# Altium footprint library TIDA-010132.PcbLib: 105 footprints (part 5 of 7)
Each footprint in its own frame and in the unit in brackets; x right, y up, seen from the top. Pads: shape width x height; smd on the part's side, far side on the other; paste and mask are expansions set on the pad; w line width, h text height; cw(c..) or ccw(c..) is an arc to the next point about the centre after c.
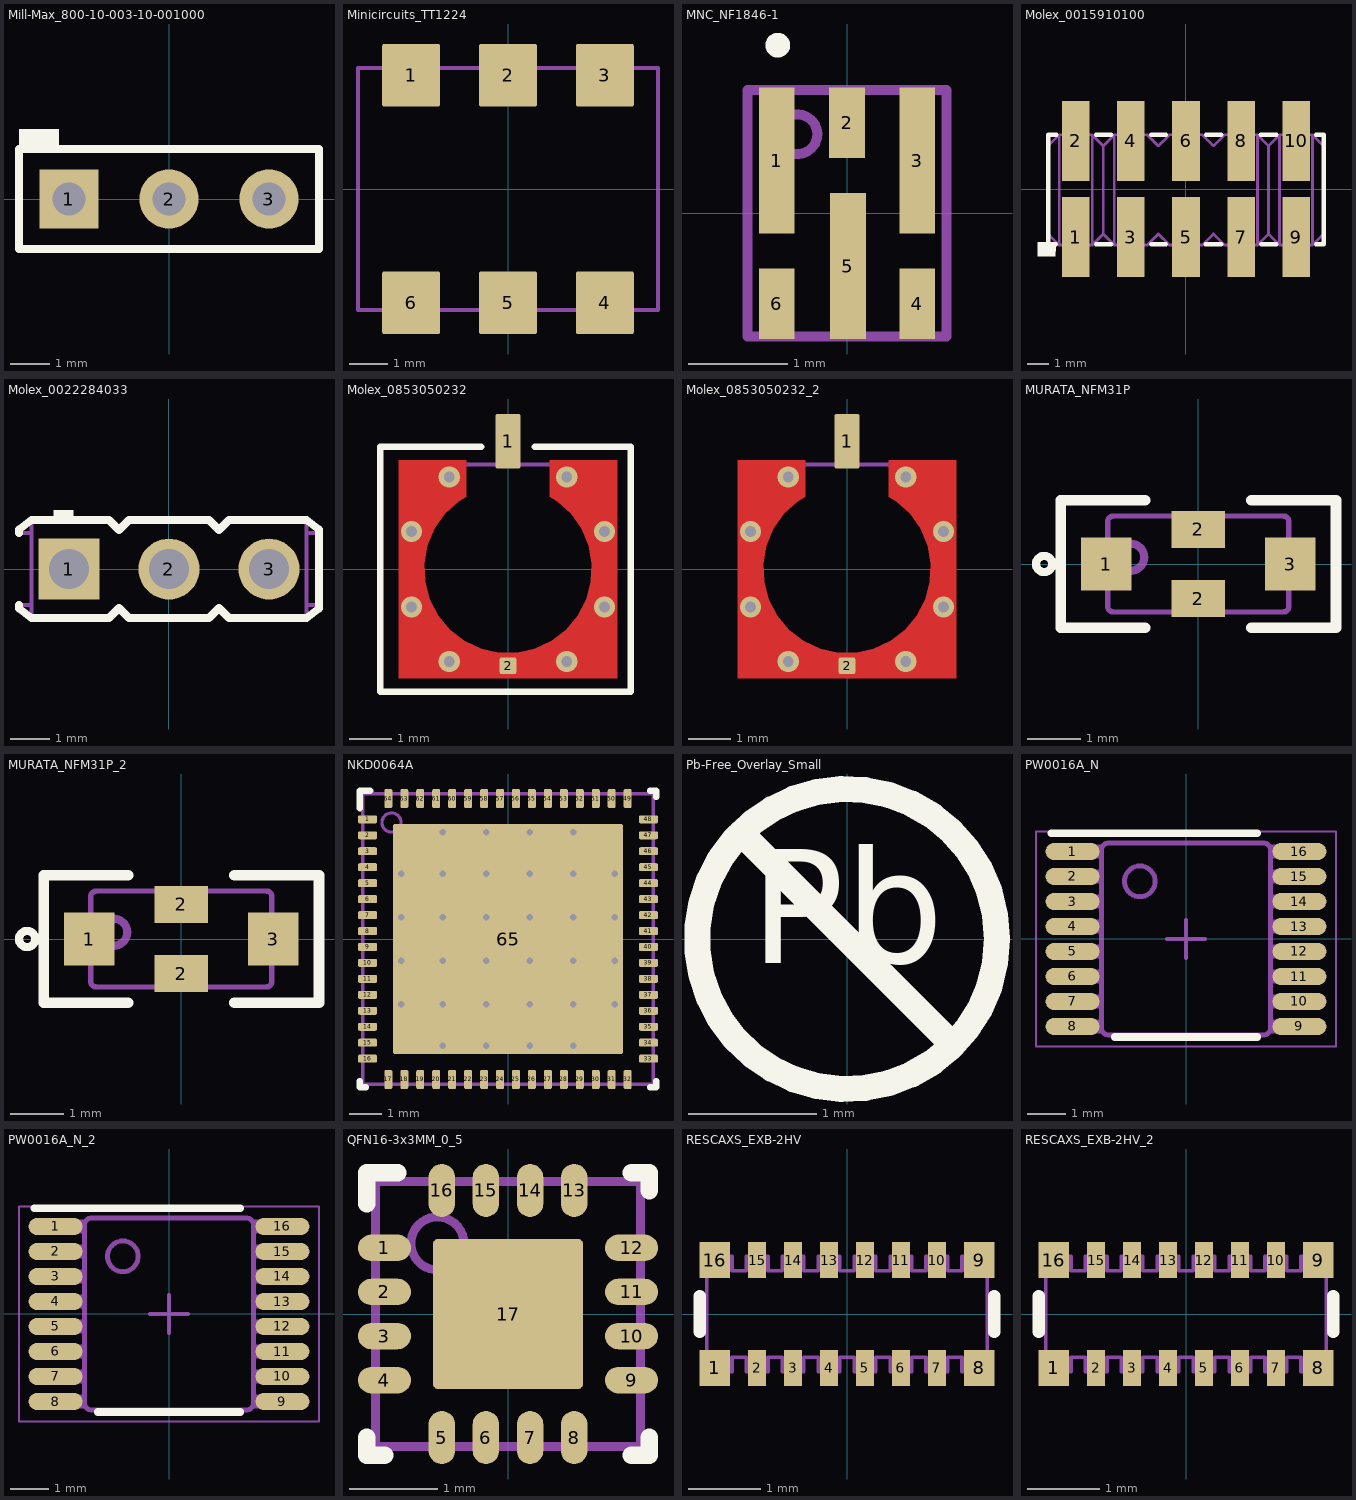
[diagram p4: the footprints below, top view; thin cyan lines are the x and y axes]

## Mill-Max_800-10-003-10-001000 [mm] "Mill-Max"
height 8.128
pads (3):
  rect 1.5x1.5 hole 0.85: 1(-2.54,0)
  round 1.5 hole 0.85: 2(0,0) 3(2.54,0)
Top Overlay:
  rectangle: -3.81,1.27 -2.794,1.778
  lines w0.203: -3.81,-1.27 3.81,-1.27 3.81,1.27 -3.81,1.27 -3.81,-1.27
Mechanical 5:
  lines w0.102: -3.81,-1.27 -3.81,1.27 3.81,1.27 3.81,-1.27 -3.81,-1.27
  text ".Designator" at -2.032,-0.508 h0.46
3D body: height 8.13, standoff 0, extent 2.162,-0.38 2.921,0.38
3D body: height 8.13, standoff 0, extent -0.378,-0.38 0.381,0.38
3D body: height 8.13, standoff 0, extent -2.918,-0.38 -2.159,0.38
3D body: height 0.81, standoff -3, extent 2.238,-0.304 2.845,0.304
3D body: height 0.81, standoff -3, extent -0.302,-0.304 0.305,0.304
3D body: height 0.81, standoff -3, extent -2.842,-0.304 -2.235,0.304
3D body: height 3.17, standoff 0, extent -3.809,-1.269 3.809,1.269

## Minicircuits_TT1224 [mm] "SMD, 6-Leads, Body 7.87x6.35mm"
height 4.06
pads (6):
  rrect7% 1.52x1.65 smd: 1(-2.54,2.985) 2(0,2.985) 3(2.54,2.985) 4(2.54,-2.985) 5(0,-2.985) 6(-2.54,-2.985)
Mechanical 5:
  lines w0.1: -3.935,-3.175 3.935,-3.175 3.935,3.175 -3.935,3.175 -3.935,-3.175
  text ".Designator" at -1.8,-0.514 h0.46
3D body: height 4.06, standoff 0, extent -3.935,-3.175 3.935,3.175

## MNC_NF1846-1 [mm] "SMD, 6-Leads, Body 2.01x2.49mm"
height 0.89
pads (6):
  rect 0.36x1.475 smd: 1(-0.71,0.533) 3(0.71,0.533) 5(0.01,-0.533)
  rect 0.36x0.71 smd: 2(0,0.915) 4(0.71,-0.915) 6(-0.71,-0.915)
Top Overlay:
  circle w0.125: c-0.7,1.7 r0.062
Mechanical 5:
  circle w0.1: c-0.5,0.8 r0.2
  lines w0.1: -1.005,-1.245 -1.005,1.245 1.005,1.245 1.005,-1.245 -1.005,-1.245
  text ".Designator" at -0.9,-0.2 h0.46
3D body: height 0.89, standoff 0, extent -1.005,-1.245 1.005,1.245
3D body: height 0.89, standoff 0.89, extent -0.699,0.601 -0.301,0.999

## Molex_0015910100 [mm] "MOLEX"
height 9.7
pads (10):
  rect 1.27x3.68 smd: 1(-5.08,-2.22) 2(-5.08,2.22) 3(-2.54,-2.22) 4(-2.54,2.22) 5(0,-2.22) 6(0,2.22) 7(2.54,-2.22) 8(2.54,2.22) 9(5.08,-2.22) 10(5.08,2.22)
Top Overlay:
  rectangle: -6.85,-3.125 -6.025,-2.45
  rectangle: -6.6,-2.875 -6,-2.45
  lines w0.2: -6,-2.55 -6.35,-2.55 -6.35,2.5 -5.975,2.5 ; -4.15,-2.55 -3.45,-2.55 ; -4.15,2.5 -3.45,2.5 ; -1.6,-2.55 -0.925,-2.55 ; -1.6,2.5 -0.925,2.5 ; 0.9,-2.55 1.625,-2.55 ; 0.925,2.5 1.625,2.5 ; 3.45,2.5 4.175,2.5 ; 3.475,-2.55 4.175,-2.55 ; 6,-2.55 6.35,-2.55 6.35,2.5 6,2.5
Mechanical 5:
  drawing of 220 lines, arcs and shapes, not listed
  text ".Designator" at -1.9,-0.525 h0.46
3D body "015910100.stp": height 9.64, standoff -0.01, extent -6.35,-3.492 6.35,3.493

## Molex_0022284033 [mm] "Header, 2.54mm, 3x1, TH"
height 8.88
pads (3):
  rect 1.55x1.55 hole 1.02: 1(-2.54,0)
  round 1.55 hole 1.02: 2(0,0) 3(2.54,0)
Top Overlay:
  rectangle: -2.93,1.245 -2.43,1.5
  lines w0.2: -3.81,-0.914 -3.81,-1.003 -3.493,-1.245 -1.524,-1.245 -1.27,-0.991 -1.016,-1.245 1.016,-1.245 1.27,-0.991 1.524,-1.245 3.493,-1.245 3.81,-1.003 3.81,-0.914 3.81,0.914 3.81,1.003 3.492,1.245 1.524,1.245 1.27,0.991 1.016,1.245 -1.016,1.245 -1.27,0.991 -1.524,1.245 -3.493,1.245 -3.81,1.003 -3.81,0.914
Mechanical 5:
  lines w0.1: -3.493,-1.168 -3.493,1.168 ; -3.492,-0.914 -3.81,-0.914 -3.81,-1.003 -3.493,-1.245 -1.524,-1.245 -1.27,-0.991 -1.016,-1.245 1.016,-1.245 1.27,-0.991 1.524,-1.245 3.493,-1.245 3.81,-1.003 3.81,-0.914 ; -3.492,0.914 -3.81,0.914 -3.81,1.003 -3.493,1.245 -1.524,1.245 -1.27,0.991 -1.016,1.245 1.016,1.245 1.27,0.991 1.524,1.245 3.492,1.245 3.81,1.003 3.81,0.914 ; 3.492,-1.168 3.492,1.168 ; 3.492,-0.914 3.81,-0.914 ; 3.492,0.914 3.81,0.914 ; 3.81,-0.914 3.81,0.914
  text ".Designator" at -2,-0.7 h0.46
3D body "022284033.stp": height 8.4, standoff -3.16, extent -3.81,-1.244 3.81,1.245

## Molex_0853050232 [mm] "Plug, 50 Ohm, Straight, SMT"
height 4.35
pads (2):
  rrect17% 0.6x1.3 smd: 1(0,3.05)
  rrect25% 0.4x0.4 smd: 2(0,-2.3)
via -2.3,0.9 diameter 0.508 hole 0.254
via -1.4,2.2 diameter 0.508 hole 0.254
via 1.4,2.2 diameter 0.508 hole 0.254
via 1.4,-2.2 diameter 0.508 hole 0.254
via -1.4,-2.2 diameter 0.508 hole 0.254
via 2.3,0.9 diameter 0.508 hole 0.254
via 2.3,-0.9 diameter 0.508 hole 0.254
via -2.3,-0.9 diameter 0.508 hole 0.254
Top Layer:
  region: -2.6,-2.6 -2.6,2.6 -1,2.6 -1,1.732 -1.183,1.613 -1.504,1.319 -1.753,0.962 -1.92,0.56 -1.996,0.131 -1.977,-0.304 -1.864,-0.725 -1.663,-1.111 -1.383,-1.445 -1.038,-1.71 -0.643,-1.894 -0.218,-1.988 0.218,-1.988 0.643,-1.894 1.038,-1.71 1.383,-1.445 1.663,-1.111 1.864,-0.725 1.977,-0.304 1.996,0.131 1.92,0.56 1.753,0.962 1.504,1.319 1.183,1.613 1,1.732 1,2.6 2.6,2.6 2.6,-2.6
Top Overlay:
  lines w0.152: -0.635,2.921 -3.048,2.921 -3.048,-2.921 2.794,-2.921 2.921,-2.921 2.921,2.921 0.635,2.921
Mechanical 5:
  lines w0.1: -0.2,2.5 -0.2,3.494 cw(c0,0.025) 0.2,3.494 0.2,2.5 ; -2.5,-1.261 ccw(c0,0) -1.261,-2.5 ; -2.5,-1.261 -2.5,-2.077 ccw(c0,0) -2.077,-2.5 -1.261,-2.5 ; -2.5,-1.261 -2.5,1.261 ; -2.5,1.261 cw(c0,0) -1.261,2.5 ; -2.5,1.261 -2.5,2.077 cw(c0,0) -2.077,2.5 -1.261,2.5 ; -1.261,-2.5 1.261,-2.5 ; -1.261,2.5 1.261,2.5 ; 1.261,-2.5 ccw(c0,0) 2.5,-1.261 ; 1.261,-2.5 2.077,-2.5 ccw(c0,0) 2.5,-2.077 2.5,-1.261 ; 1.261,2.5 cw(c0,0) 2.5,1.261 ; 1.261,2.5 2.077,2.5 cw(c0,0) 2.5,2.077 2.5,1.261 ; 2.5,-1.261 2.5,1.261
  text ".Designator" at -1.6,-0.3 h0.46
3D body "0853050232.stp": height 4.1, standoff 0, extent -2.5,-2.5 2.5,3.5

## Molex_0853050232_2 [mm]
pads (2):
  rrect17% 0.6x1.3 smd: 1(0,3.05)
  rrect25% 0.4x0.4 smd: 2(0,-2.3)
via -2.3,0.9 diameter 0.508 hole 0.254
via -1.4,2.2 diameter 0.508 hole 0.254
via 1.4,2.2 diameter 0.508 hole 0.254
via 1.4,-2.2 diameter 0.508 hole 0.254
via -1.4,-2.2 diameter 0.508 hole 0.254
via 2.3,0.9 diameter 0.508 hole 0.254
via 2.3,-0.9 diameter 0.508 hole 0.254
via -2.3,-0.9 diameter 0.508 hole 0.254
Top Layer:
  region: -2.6,-2.6 -2.6,2.6 -1,2.6 -1,1.732 -1.183,1.613 -1.504,1.319 -1.753,0.962 -1.92,0.56 -1.996,0.131 -1.977,-0.304 -1.864,-0.725 -1.663,-1.111 -1.383,-1.445 -1.038,-1.71 -0.643,-1.894 -0.218,-1.988 0.218,-1.988 0.643,-1.894 1.038,-1.71 1.383,-1.445 1.663,-1.111 1.864,-0.725 1.977,-0.304 1.996,0.131 1.92,0.56 1.753,0.962 1.504,1.319 1.183,1.613 1,1.732 1,2.6 2.6,2.6 2.6,-2.6
Mechanical 5:
  lines w0.1: -0.2,2.5 -0.2,3.494 cw(c0,0.025) 0.2,3.494 0.2,2.5 ; -2.5,-1.261 ccw(c0,0) -1.261,-2.5 ; -2.5,-1.261 -2.5,-2.077 ccw(c0,0) -2.077,-2.5 -1.261,-2.5 ; -2.5,-1.261 -2.5,1.261 ; -2.5,1.261 cw(c0,0) -1.261,2.5 ; -2.5,1.261 -2.5,2.077 cw(c0,0) -2.077,2.5 -1.261,2.5 ; -1.261,-2.5 1.261,-2.5 ; -1.261,2.5 1.261,2.5 ; 1.261,-2.5 ccw(c0,0) 2.5,-1.261 ; 1.261,-2.5 2.077,-2.5 ccw(c0,0) 2.5,-2.077 2.5,-1.261 ; 1.261,2.5 cw(c0,0) 2.5,1.261 ; 1.261,2.5 2.077,2.5 cw(c0,0) 2.5,2.077 2.5,1.261 ; 2.5,-1.261 2.5,1.261
  text ".Designator" at -1.6,-0.3 h0.46
3D body "0853050232.stp": height 4.1, standoff 0, extent -2.5,-2.5 2.5,3.5

## MURATA_NFM31P [mm] "SMD, 3-Leads, Body 3.2x1.6mm"
height 1.5
pads (4):
  rect 0.95x1 smd paste-2 mask-2: 1(-1.725,0) 3(1.725,0)
  rect 1x0.7 smd paste-2 mask+0: 2(0,-0.65) 2(0,0.65)
Top Overlay:
  circle w0.152: c-2.896,0 r0.152
  lines w0.2: -1,-1.2 -2.586,-1.2 -2.586,1.2 -1,1.2 ; 1,-1.2 2.586,-1.2 2.586,1.2 1,1.2
Top Paste:
  region: -1.25,0.6 -2.2,0.6 -2.2,-0.6 -1.25,-0.6
  rectangle: 1.25,-0.6 2.2,0.6
  region: 0.5,-0.3 -0.5,-0.3 -0.5,-1.3 0.5,-1.3
  rectangle: -0.5,0.3 0.5,1.3
Top Solder:
  rectangle: 0.7,-1 2.2,1
  region: -0.7,1 -2.2,1 -2.2,-1 -0.7,-1
Mechanical 5:
  circle w0.152: c-1.27,0.127 r0.254
  lines w0.1: -1.7,-0.8 ccw(c-1.6,-0.8) -1.6,-0.9 1.6,-0.9 ccw(c1.6,-0.8) 1.7,-0.8 1.7,0.8 ccw(c1.6,0.8) 1.6,0.9 -1.6,0.9 ccw(c-1.6,0.8) -1.7,0.8 -1.7,-0.8
  text ".Designator" at -0.975,-0.3 h0.46
3D body "NFM31PC276B0J3L.stp": height 1.5, standoff 0, extent -1.7,-0.9 1.7,0.9

## MURATA_NFM31P_2 [mm]
pads (4):
  rect 0.95x1 smd paste-2 mask-2: 1(-1.725,0) 3(1.725,0)
  rect 1x0.7 smd paste-2 mask+0: 2(0,-0.65) 2(0,0.65)
Top Overlay:
  circle w0.152: c-2.896,0 r0.152
  lines w0.2: -1,-1.2 -2.586,-1.2 -2.586,1.2 -1,1.2 ; 1,-1.2 2.586,-1.2 2.586,1.2 1,1.2
Top Paste:
  rectangle: -0.5,0.3 0.5,1.3
  region: 0.5,-0.3 -0.5,-0.3 -0.5,-1.3 0.5,-1.3
  rectangle: 1.25,-0.6 2.2,0.6
  region: -1.25,0.6 -2.2,0.6 -2.2,-0.6 -1.25,-0.6
Top Solder:
  region: -0.7,1 -2.2,1 -2.2,-1 -0.7,-1
  rectangle: 0.7,-1 2.2,1
Mechanical 5:
  circle w0.152: c-1.27,0.127 r0.254
  lines w0.1: -1.7,-0.8 ccw(c-1.6,-0.8) -1.6,-0.9 1.6,-0.9 ccw(c1.6,-0.8) 1.7,-0.8 1.7,0.8 ccw(c1.6,0.8) 1.6,0.9 -1.6,0.9 ccw(c-1.6,0.8) -1.7,0.8 -1.7,-0.8
  text ".Designator" at -0.975,-0.3 h0.46
3D body "NFM31PC276B0J3L.stp": height 1.5, standoff 0, extent -1.7,-0.9 1.7,0.9

## NKD0064A [mm] "QFN, 64-Leads, Body 9x9mm, Pitch 0.5mm"
height 0.8
pads (65):
  rrect40% 0.6x0.25 smd: 1(-4.4,3.75) 2(-4.4,3.25) 3(-4.4,2.75) 4(-4.4,2.25) 5(-4.4,1.75) 6(-4.4,1.25) 7(-4.4,0.75) 8(-4.4,0.25) 9(-4.4,-0.25) 10(-4.4,-0.75) 11(-4.4,-1.25) 12(-4.4,-1.75) 13(-4.4,-2.25) 14(-4.4,-2.75) 15(-4.4,-3.25) 16(-4.4,-3.75) 33(4.4,-3.75) 34(4.4,-3.25) 35(4.4,-2.75) 36(4.4,-2.25) 37(4.4,-1.75) 38(4.4,-1.25) 39(4.4,-0.75) 40(4.4,-0.25) 41(4.4,0.25) 42(4.4,0.75) 43(4.4,1.25) 44(4.4,1.75) 45(4.4,2.25) 46(4.4,2.75) 47(4.4,3.25) 48(4.4,3.75)
  rrect40% 0.25x0.6 smd: 17(-3.75,-4.4) 18(-3.25,-4.4) 19(-2.75,-4.4) 20(-2.25,-4.4) 21(-1.75,-4.4) 22(-1.25,-4.4) 23(-0.75,-4.4) 24(-0.25,-4.4) 25(0.25,-4.4) 26(0.75,-4.4) 27(1.25,-4.4) 28(1.75,-4.4) 29(2.25,-4.4) 30(2.75,-4.4) 31(3.25,-4.4) 32(3.75,-4.4) 49(3.75,4.4) 50(3.25,4.4) 51(2.75,4.4) 52(2.25,4.4) 53(1.75,4.4) 54(1.25,4.4) 55(0.75,4.4) 56(0.25,4.4) 57(-0.25,4.4) 58(-0.75,4.4) 59(-1.25,4.4) 60(-1.75,4.4) 61(-2.25,4.4) 62(-2.75,4.4) 63(-3.25,4.4) 64(-3.75,4.4)
  rrect1% 7.2x7.2 smd paste-3.6: 65(0,0)
via 3.35,0.68 diameter 0.5 hole 0.2
via 3.35,2.04 diameter 0.5 hole 0.2
via -3.35,0.68 diameter 0.5 hole 0.2
via -3.35,2.04 diameter 0.5 hole 0.2
via 3.35,-2.04 diameter 0.5 hole 0.2
via 3.35,-0.68 diameter 0.5 hole 0.2
via -2.04,-3.35 diameter 0.5 hole 0.2
via -0.68,-3.35 diameter 0.5 hole 0.2
via 2.04,-3.35 diameter 0.5 hole 0.2
via 0.68,-3.35 diameter 0.5 hole 0.2
via 2.04,3.35 diameter 0.5 hole 0.2
via 0.68,3.35 diameter 0.5 hole 0.2
via -0.68,3.35 diameter 0.5 hole 0.2
via -2.04,3.35 diameter 0.5 hole 0.2
via 2.04,2.04 diameter 0.5 hole 0.2
via 0.68,2.04 diameter 0.5 hole 0.2
via -0.68,2.04 diameter 0.5 hole 0.2
via -2.04,2.04 diameter 0.5 hole 0.2
via 2.04,-2.04 diameter 0.5 hole 0.2
via 0.68,-2.04 diameter 0.5 hole 0.2
via -0.68,-2.04 diameter 0.5 hole 0.2
via -2.04,-2.04 diameter 0.5 hole 0.2
via -2.04,-0.68 diameter 0.5 hole 0.2
via 2.04,-0.68 diameter 0.5 hole 0.2
via 2.04,0.68 diameter 0.5 hole 0.2
via -2.04,0.68 diameter 0.5 hole 0.2
via 0.68,-0.68 diameter 0.5 hole 0.2
via -0.68,-0.68 diameter 0.5 hole 0.2
via -0.68,0.68 diameter 0.5 hole 0.2
via 0.68,0.68 diameter 0.5 hole 0.2
via -3.35,-0.68 diameter 0.5 hole 0.2
via -3.35,-2.04 diameter 0.5 hole 0.2
Top Overlay:
  lines w0.2: -4.65,-4.45 -4.65,-4.65 -4.45,-4.65 ; -4.65,4.1 -4.65,4.65 -4.32,4.65 ; 4.45,-4.65 4.65,-4.65 4.65,-4.45 ; 4.45,4.65 4.65,4.65 4.65,4.45
Top Paste:
  rectangle: -3.3,-3.3 -2.14,-2.14
  rectangle: -1.94,-3.3 -0.78,-2.14
  rectangle: -0.58,-3.3 0.58,-2.14
  rectangle: 0.78,-3.3 1.94,-2.14
  rectangle: 2.14,-3.3 3.3,-2.14
  rectangle: 2.14,-1.94 3.3,-0.78
  rectangle: 0.78,-1.94 1.94,-0.78
  rectangle: -0.58,-1.94 0.58,-0.78
  rectangle: -1.94,-1.94 -0.78,-0.78
  rectangle: -3.3,-1.94 -2.14,-0.78
  rectangle: -3.3,-0.58 -2.14,0.58
  rectangle: -1.94,-0.58 -0.78,0.58
  rectangle: -1.94,0.78 -0.78,1.94
  rectangle: -3.3,0.78 -2.14,1.94
  rectangle: -3.3,2.14 -2.14,3.3
  rectangle: -1.94,2.14 -0.78,3.3
  rectangle: -0.58,2.14 0.58,3.3
  rectangle: -0.58,0.78 0.58,1.94
  rectangle: 2.14,0.78 3.3,1.94
  rectangle: 2.14,2.14 3.3,3.3
  rectangle: 0.78,2.14 1.94,3.3
  rectangle: 0.78,0.78 1.94,1.94
  rectangle: 2.14,-0.58 3.3,0.58
  rectangle: 0.78,-0.58 1.94,0.58
  rectangle: -0.58,-0.58 0.58,0.58
Mechanical 5:
  circle w0.1: c-3.65,3.65 r0.3
  lines w0.1: -4.55,-4.55 4.55,-4.55 4.55,4.55 -4.55,4.55 -4.55,-4.55
  text ".Designator" at -1.524,-0.508 h0.46
3D body: height 0.8, standoff 0, extent -4.549,-4.549 4.549,4.549
3D body: height 0.81, standoff 0.5, extent -3.949,3.351 -3.351,3.949

## Pb-Free_Overlay_Small [mil]
Top Overlay:
  circle w8: c0,0 r46
  lines w8: -32.53,32.53 32.53,-32.53
  text "Pb" at -29.6,-18.9 h60

## PW0016A_N [mm] "TSOP, 16-Leads, Body 5x4.4mm, Pitch 0.65mm, IPC Medium Density"
height 1.2
pads (16):
  oval 1.4x0.45 smd: 1(-2.95,2.275) 2(-2.95,1.625) 3(-2.95,0.975) 4(-2.95,0.325) 5(-2.95,-0.325) 6(-2.95,-0.975) 7(-2.95,-1.625) 8(-2.95,-2.275) 9(2.95,-2.275) 10(2.95,-1.625) 11(2.95,-0.975) 12(2.95,-0.325) 13(2.95,0.325) 14(2.95,0.975) 15(2.95,1.625) 16(2.95,2.275)
Top Overlay:
  lines w0.2: -3.5,2.75 1.85,2.75 ; -1.85,-2.55 1.85,-2.55
Mechanical 5:
  drawing of 202 lines, arcs and shapes, not listed
  text ".Designator" at -1.854,-0.508 h0.46
Mechanical 15:
  lines w0.05: -3.9,-2.8 3.9,-2.8 3.9,2.8 -3.9,2.8 -3.9,-2.8
  lines w0.1: -0.5,0 0.5,0 ; 0,-0.5 0,0.5
3D body "PW0016A.stp": height 1, standoff 0, extent -3.21,-2.5 3.21,2.5

## PW0016A_N_2 [mm]
pads (16):
  oval 1.4x0.45 smd: 1(-2.95,2.275) 2(-2.95,1.625) 3(-2.95,0.975) 4(-2.95,0.325) 5(-2.95,-0.325) 6(-2.95,-0.975) 7(-2.95,-1.625) 8(-2.95,-2.275) 9(2.95,-2.275) 10(2.95,-1.625) 11(2.95,-0.975) 12(2.95,-0.325) 13(2.95,0.325) 14(2.95,0.975) 15(2.95,1.625) 16(2.95,2.275)
Top Overlay:
  lines w0.2: -3.5,2.75 1.85,2.75 ; -1.85,-2.55 1.85,-2.55
Mechanical 5:
  drawing of 202 lines, arcs and shapes, not listed
  text ".Designator" at -1.854,-0.508 h0.46
Mechanical 15:
  lines w0.05: -3.9,-2.8 3.9,-2.8 3.9,2.8 -3.9,2.8 -3.9,-2.8
  lines w0.1: -0.5,0 0.5,0 ; 0,-0.5 0,0.5
3D body "PW0016A.stp": height 1, standoff 0, extent -3.21,-2.5 3.21,2.5

## QFN16-3x3MM_0_5 [mm] "QFN, 16-Leads, Body 3x3mm, Pitch 0.5mm"
height 1
pads (17):
  rrect100% 0.6x0.3 smd: 1(-1.4,0.75) 2(-1.4,0.25) 3(-1.4,-0.25) 4(-1.4,-0.75) 9(1.4,-0.75) 10(1.4,-0.25) 11(1.4,0.25) 12(1.4,0.75)
  rrect100% 0.3x0.6 smd: 5(-0.75,-1.4) 6(-0.25,-1.4) 7(0.25,-1.4) 8(0.75,-1.4) 13(0.75,1.4) 14(0.25,1.4) 15(-0.25,1.4) 16(-0.75,1.4)
  rrect6% 1.7x1.7 smd paste-2: 17(0,0)
Top Overlay:
  lines w0.2: -1.6,-1.4 -1.6,-1.6 -1.4,-1.6 ; -1.6,1.25 -1.6,1.6 -1.25,1.6 ; 1.4,-1.6 1.6,-1.6 1.6,-1.4 ; 1.4,1.6 1.6,1.6 1.6,1.4
Top Paste:
  rectangle: -0.774,-0.774 0.775,0.775
Mechanical 5:
  circle w0.1: c-0.8,0.8 r0.3
  lines w0.1: -1.5,-1.5 -1.5,1.5 1.5,1.5 1.5,-1.5 -1.5,-1.5
  text ".Designator" at 0,-0.127 h0.46
3D body: height 1.01, standoff 1, extent -1.099,0.501 -0.501,1.099
3D body: height 1, standoff 0, extent -1.5,-1.5 1.5,1.5

## RESCAXS_EXB-2HV [mm] "Panasonic Resistor Array"
height 0.55
pads (16):
  rect 0.425x0.5 smd mask+0.07: 1(-1.837,-0.75) 8(1.837,-0.75) 9(1.837,0.75) 16(-1.837,0.75)
  rect 0.25x0.5 smd mask+0.07: 2(-1.25,-0.75) 3(-0.75,-0.75) 4(-0.25,-0.75) 5(0.25,-0.75) 6(0.75,-0.75) 7(1.25,-0.75) 10(1.25,0.75) 11(0.75,0.75) 12(0.25,0.75) 13(-0.25,0.75) 14(-0.75,0.75) 15(-1.25,0.75)
Top Overlay:
  lines w0.17: -2.05,-0.25 -2.05,0.25 ; 2.05,-0.25 2.05,0.25
Mechanical 5:
  lines w0.05: -1.95,-0.8 -1.95,0.8 -1.6,0.8 -1.6,0.6 -1.4,0.6 -1.4,0.8 -1.1,0.8 -1.1,0.6 -0.9,0.6 -0.9,0.8 -0.6,0.8 -0.6,0.6 -0.4,0.6 -0.4,0.8 -0.1,0.8 -0.1,0.6 0.1,0.6 0.1,0.8 0.4,0.8 0.4,0.6 0.6,0.6 0.6,0.8 0.9,0.8 0.9,0.6 1.1,0.6 1.1,0.8 1.4,0.8 1.4,0.6 1.6,0.6 1.6,0.8 1.95,0.8 1.95,-0.8 1.6,-0.8 1.6,-0.6 1.4,-0.6 1.4,-0.8 1.1,-0.8 1.1,-0.6 0.9,-0.6 0.9,-0.8 0.6,-0.8 0.6,-0.6 0.4,-0.6 0.4,-0.8 0.1,-0.8 0.1,-0.6 -0.1,-0.6 -0.1,-0.8 -0.4,-0.8 -0.4,-0.6 -0.6,-0.6 -0.6,-0.8 -0.9,-0.8 -0.9,-0.6 -1.1,-0.6 -1.1,-0.8 -1.4,-0.8 -1.4,-0.6 -1.6,-0.6 -1.6,-0.8 -1.95,-0.8
  text ".Designator" at -0.9,-0.25 h0.46
3D body: height 0.55, standoff 0, extent -1.949,-0.799 1.949,0.799
3D body: height 0.55, standoff 0.52, extent -1.949,-0.449 1.949,0.449

## RESCAXS_EXB-2HV_2 [mm]
pads (16):
  rect 0.425x0.5 smd mask+0.07: 1(-1.837,-0.75) 8(1.837,-0.75) 9(1.837,0.75) 16(-1.837,0.75)
  rect 0.25x0.5 smd mask+0.07: 2(-1.25,-0.75) 3(-0.75,-0.75) 4(-0.25,-0.75) 5(0.25,-0.75) 6(0.75,-0.75) 7(1.25,-0.75) 10(1.25,0.75) 11(0.75,0.75) 12(0.25,0.75) 13(-0.25,0.75) 14(-0.75,0.75) 15(-1.25,0.75)
Top Overlay:
  lines w0.17: -2.05,-0.25 -2.05,0.25 ; 2.05,-0.25 2.05,0.25
Mechanical 5:
  lines w0.05: -1.95,-0.8 -1.6,-0.8 -1.6,-0.6 -1.4,-0.6 -1.4,-0.8 -1.1,-0.8 -1.1,-0.6 -0.9,-0.6 -0.9,-0.8 -0.6,-0.8 -0.6,-0.6 -0.4,-0.6 -0.4,-0.8 -0.1,-0.8 -0.1,-0.6 0.1,-0.6 0.1,-0.8 0.4,-0.8 0.4,-0.6 0.6,-0.6 0.6,-0.8 0.9,-0.8 0.9,-0.6 1.1,-0.6 1.1,-0.8 1.4,-0.8 1.4,-0.6 1.6,-0.6 1.6,-0.8 1.95,-0.8 1.95,0.8 1.6,0.8 1.6,0.6 1.4,0.6 1.4,0.8 1.1,0.8 1.1,0.6 0.9,0.6 0.9,0.8 0.6,0.8 0.6,0.6 0.4,0.6 0.4,0.8 0.1,0.8 0.1,0.6 -0.1,0.6 -0.1,0.8 -0.4,0.8 -0.4,0.6 -0.6,0.6 -0.6,0.8 -0.9,0.8 -0.9,0.6 -1.1,0.6 -1.1,0.8 -1.4,0.8 -1.4,0.6 -1.6,0.6 -1.6,0.8 -1.95,0.8 -1.95,-0.8
  text ".Designator" at -0.9,-0.25 h0.46
3D body: height 0.55, standoff 0.52, extent -1.949,-0.449 1.949,0.449
3D body: height 0.55, standoff 0, extent -1.949,-0.799 1.949,0.799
